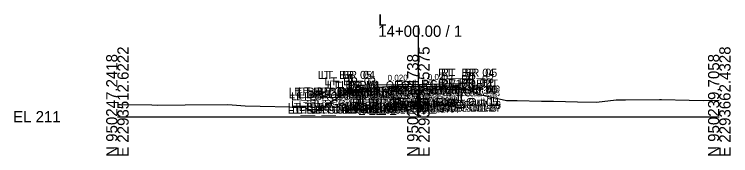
# Model space of a CAD drawing. Extents: x -26 to 7053, y -10 to 7035.
# Drawn here: x -25.7 to 152.8, y 3990.3 to 4025.5 of the extents above; entities that cross this region are included whole.
import ezdxf

# ---------------------------------------------------------------- set-up
doc = ezdxf.new("R2010")
doc.units = 0
for name, color, linetype in [('Default', 7, 'Continuous'), ('Exist Cross Section Cell', 7, 'Continuous'), ('Exist XS Center Line Elevation Label', 7, 'Continuous'), ('Exist XS Ground Line', 7, 'Continuous'), ('Prop CMT Concrete Structures', 7, 'Continuous'), ('Prop XS SE Text', 7, 'Continuous')]:
    doc.layers.add(name, color=color, linetype=linetype)

msp = doc.modelspace()

# ---------------------------------------------------------------- linework, layer by layer
at = {"layer": 'Exist Cross Section Cell'}
for p, q in [((75, 4000), (75, 4022.68)), ((0, 4000), (75, 4000)), ((75, 4000), (150, 4000))]:
    msp.add_line(p, q, dxfattribs=at)
at = {"layer": 'Exist XS Ground Line'}
for p, q in [((56.46, 4005.8), (57.9, 4006.48)), ((57.9, 4006.48), (60.01, 4006.89)), ((60.01, 4006.89), (60.45, 4006.78)), ((60.45, 4006.78), (62.02, 4006.92)), ((62.02, 4006.92), (62.81, 4007.21)), ((62.81, 4007.21), (67.59, 4007.48)), ((67.59, 4007.48), (72.22, 4007.51)), ((72.22, 4007.51), (75, 4007.55)), ((75, 4007.55), (75.33, 4007.56)), ((75.33, 4007.56), (78.52, 4007.5)), ((78.52, 4007.5), (82.94, 4007.47)), ((82.94, 4007.47), (85.14, 4007.27)), ((85.14, 4007.27), (85.96, 4007.16)), ((85.96, 4007.16), (86.55, 4006.97)), ((86.55, 4006.97), (89.94, 4005.6)), ((52.18, 4002.98), (56.46, 4005.8)), ((89.94, 4005.6), (96.93, 4004.06)), ((0, 4003.05), (0.18, 4003.05)), ((0.18, 4003.05), (0.73, 4003.04)), ((0.73, 4003.04), (8.6, 4002.98)), ((8.6, 4002.98), (9.89, 4002.89)), ((9.89, 4002.89), (16.9, 4002.98)), ((16.9, 4002.98), (27.54, 4003)), ((27.54, 4003), (31.88, 4002.74)), ((31.88, 4002.74), (46.75, 4002.38)), ((50.88, 4002.04), (52.18, 4002.98)), ((96.93, 4004.06), (99.63, 4004.01)), ((99.63, 4004.01), (105.72, 4003.86)), ((105.72, 4003.86), (106.09, 4003.86)), ((106.09, 4003.86), (108.72, 4003.86)), ((108.72, 4003.86), (114.7, 4003.73)), ((114.7, 4003.73), (119.42, 4003.66)), ((119.42, 4003.66), (124.32, 4004.24)), ((124.32, 4004.24), (126.28, 4004.19)), ((126.28, 4004.19), (126.62, 4004.17)), ((126.62, 4004.17), (135.09, 4004.26)), ((135.09, 4004.26), (135.64, 4004.28)), ((135.64, 4004.28), (142.53, 4004.14)), ((142.53, 4004.14), (145.99, 4004.03)), ((145.99, 4004.03), (150, 4004.11)), ((46.75, 4002.38), (48.59, 4001.23)), ((48.59, 4001.23), (48.77, 4000.78)), ((48.77, 4000.78), (49.04, 4001.22)), ((49.04, 4001.22), (50.88, 4002.04))]:
    msp.add_line(p, q, dxfattribs=at)
at = {"layer": 'Prop CMT Concrete Structures'}
for points in [[(75, 4008.05), (65, 4007.85), (59.17, 4007.73), (59.16, 4007.98), (58.58, 4008.81), (58.41, 4010.4), (57.67, 4010.4), (57.67, 4006.2)], [(75, 4008.05), (85, 4008.25), (87, 4008.29), (87.01, 4008.54), (87.59, 4009.37), (87.76, 4010.95), (88.5, 4010.95), (88.5, 4006.82)], [(57.67, 4006.2), (65, 4006.35), (75, 4006.55)], [(61.63, 4006.28), (60.79, 4006.26), (59.96, 4006.24)], [(61.63, 4005.59), (61.63, 4006.28)], [(75, 4006.55), (74.17, 4006.53)], [(74.17, 4006.53), (74.17, 4005.88)], [(75, 4006.55), (75, 4008.05)], [(75, 4006.55), (75, 4008.05)], [(88.5, 4006.82), (85, 4006.75), (75, 4006.55)], [(75, 4006.55), (75.83, 4006.56)], [(75, 4002.04), (75, 4006.55)], [(75, 4002.04), (75, 4006.55)], [(75.83, 4006.56), (75.83, 4005.88)], [(84.54, 4006.74), (85.38, 4006.75), (86.21, 4006.77)], [(84.54, 4006.09), (84.54, 4006.74)], [(86.21, 4006.77), (86.21, 4006.09)], [(59.96, 4006.24), (59.96, 4005.59)], [(59.96, 4005.59), (60.46, 4005.09)], [(60.46, 4005.09), (60.46, 4003.18)], [(61.13, 4005.09), (61.63, 4005.59)], [(61.13, 4003.18), (61.13, 4005.09)], [(74.17, 4005.88), (74.67, 4005.38)], [(74.67, 4005.38), (74.67, 4003.46)], [(75.83, 4005.88), (75.33, 4005.38)], [(75.33, 4005.38), (75.33, 4003.46)], [(85.04, 4005.59), (84.54, 4006.09)], [(85.04, 4003.67), (85.04, 4005.59)], [(86.21, 4006.09), (85.71, 4005.59)], [(85.71, 4005.59), (85.71, 4003.67)], [(60.46, 4003.18), (59.71, 4002.43)], [(61.88, 4002.43), (61.13, 4003.18)], [(74.67, 4003.46), (73.92, 4002.71)], [(73.92, 4002.71), (73.92, 4002.04)], [(75.33, 4003.46), (76.08, 4002.71)], [(76.08, 4002.71), (76.08, 4002.04)], [(84.29, 4002.92), (85.04, 4003.67)], [(84.29, 4002.25), (84.29, 4002.92)], [(85.71, 4003.67), (86.46, 4002.92)], [(86.46, 4002.92), (86.46, 4002.25)], [(59.71, 4002.43), (59.71, 4001.76)], [(59.71, 4001.76), (60.79, 4001.76), (61.88, 4001.76)], [(61.88, 4001.76), (61.88, 4002.43)], [(73.92, 4002.04), (75, 4002.04)], [(76.08, 4002.04), (75, 4002.04)], [(86.46, 4002.25), (85.38, 4002.25), (84.29, 4002.25)]]:
    msp.add_lwpolyline(points, dxfattribs=at)

# ---------------------------------------------------------------- texts
at = {"layer": 'Default'}
for s, height, p in [('RT_ BR_04', 2, (79.95, 4009.95)), ('RT_ BR_05', 2, (80.69, 4009.95)), ('LT_ BR_05', 2, (49.91, 4009.4)), ('LT_ BR_04', 2, (50.65, 4009.4)), ('RT_BR_03', 2, (80.6, 4008.37)), ('LT_BR_03', 2, (51.63, 4007.81)), ('LT_BR_02', 2, (52.22, 4006.98)), ('LT_BR_01', 2, (52.79, 4006.73)), ('LT_PV1_OEOT', 2, (55.74, 4006.85)), ('PV1_PGL', 2, (69.47, 4007.05)), ('RT_PV1_OEOT', 2, (75.69, 4007.25)), ('RT_BR_02', 2, (80.02, 4007.54)), ('RT_BR_01', 2, (80.57, 4007.29)), ('LT_BR_Girder Out 02', 2, (42.75, 4005.24)), ('LT_BR_Girder Out 03', 2, (42.75, 4004.59)), ('LT_BR_Girder Out 01', 2, (44.15, 4005.26)), ('LT_BR_Girder Out 14', 2, (45.06, 4005.28)), ('LT_BR_Girder Out 13', 2, (45.06, 4004.59)), ('LT_BR_06', 2, (50.68, 4005.2)), ('LT_BR_Girder Mid 02', 2, (57.35, 4005.53)), ('LT_BR_Girder Mid 03', 2, (57.35, 4004.88)), ('LT_BR_Girder Mid 04', 2, (57.85, 4004.38)), ('LT_BR_07', 2, (58.06, 4005.35)), ('RT_BR_Girder Mid 04', 2, (58.47, 4004.38)), ('RT_BR_Girder Mid 02', 2, (58.97, 4005.56)), ('RT_BR_Girder Mid 03', 2, (58.97, 4004.88)), ('RT_BR_Girder Out 14', 2, (67.93, 4005.74)), ('RT_BR_Girder Out 13', 2, (67.93, 4005.09)), ('RT_BR_Girder Out 12', 2, (68.43, 4004.59)), ('RT_BR_Girder Out 04', 2, (68.45, 4004.59)), ('RT_BR_Girder Out 01', 2, (68.68, 4005.75)), ('RT_BR_Girder Out 02', 2, (68.95, 4005.77)), ('RT_BR_Girder Out 03', 2, (68.95, 4005.09)), ('BR_PGL', 2, (69.83, 4005.55)), ('RT_BR_07', 2, (78.01, 4005.75)), ('RT_BR_06', 2, (81.46, 4005.82)), ('LT_BR_Girder Out 04', 2, (43.25, 4004.09)), ('LT_BR_Girder Out 12', 2, (44.56, 4004.09)), ('LT_BR_Girder Mid 05', 2, (57.85, 4002.46)), ('RT_BR_Girder Mid 05', 2, (58.47, 4002.46)), ('RT_BR_Girder Out 05', 2, (68.45, 4002.67)), ('RT_BR_Girder Out 11', 2, (69, 4002.67)), ('LT_BR_Girder Out 06', 2, (42.45, 4001.43)), ('LT_BR_Girder Out 07', 2, (42.5, 4000.76)), ('LT_BR_Girder Out 05', 2, (43.25, 4002.18)), ('LT_BR_Girder Out 08', 2, (43.58, 4000.76)), ('LT_BR_Girder Out 09', 2, (44.66, 4000.76)), ('LT_BR_Girder Out 11', 2, (45.13, 4002.18)), ('LT_BR_Girder Out 10', 2, (45.23, 4001.43)), ('LT_BR_Girder Mid 06', 2, (57.05, 4001.71)), ('LT_BR_Girder Mid 07', 2, (57.1, 4001.04)), ('RT_BR_Girder Mid 06', 2, (59.17, 4001.71)), ('RT_BR_Girder Mid 07', 2, (59.22, 4001.04)), ('BR_Girder Mid 08', 2, (60.87, 4001.04)), ('RT_BR_Girder Out 09', 2, (67.03, 4001.25)), ('RT_BR_Girder Out 10', 2, (67.6, 4001.92)), ('RT_BR_Girder Out 08', 2, (68.12, 4001.25)), ('RT_BR_Girder Out 06', 2, (69.15, 4001.92)), ('RT_BR_Girder Out 07', 2, (69.2, 4001.25)), ('-', 0.0001, (0, 4000))]:
    msp.add_text(s, height=height, dxfattribs=at).set_placement(p)
at = {"layer": 'Exist Cross Section Cell'}
for s, p in [('L', (65, 4022.68)), ('14+00.00 / 1', (65, 4019.88)), ('EL 211', (-26, 3998.6))]:
    msp.add_text(s, height=2.8, dxfattribs=at).set_placement(p)
for s, p in [('E 2293512.6222', (2.8, 3990)), ('E 2293587.5275', (77.8, 3990)), ('E 2293662.4328', (152.8, 3990)), ('N 950247.2418', (0, 3990)), ('N 950243.4738', (75, 3990)), ('N 950239.7058', (150, 3990))]:
    msp.add_text(s, height=2.8, rotation=90, dxfattribs=at).set_placement(p)
at = {"layer": 'Exist XS Center Line Elevation Label'}
msp.add_text('218.55', height=2, dxfattribs=at).set_placement((70.98, 4002.55))
at = {"layer": 'Prop XS SE Text'}
for p in [(67.36, 4008.89), (77.36, 4009.09)]:
    msp.add_text('0.020', height=1.5, rotation=1.1458, dxfattribs=at).set_placement(p)

doc.saveas('drawing.dxf')
